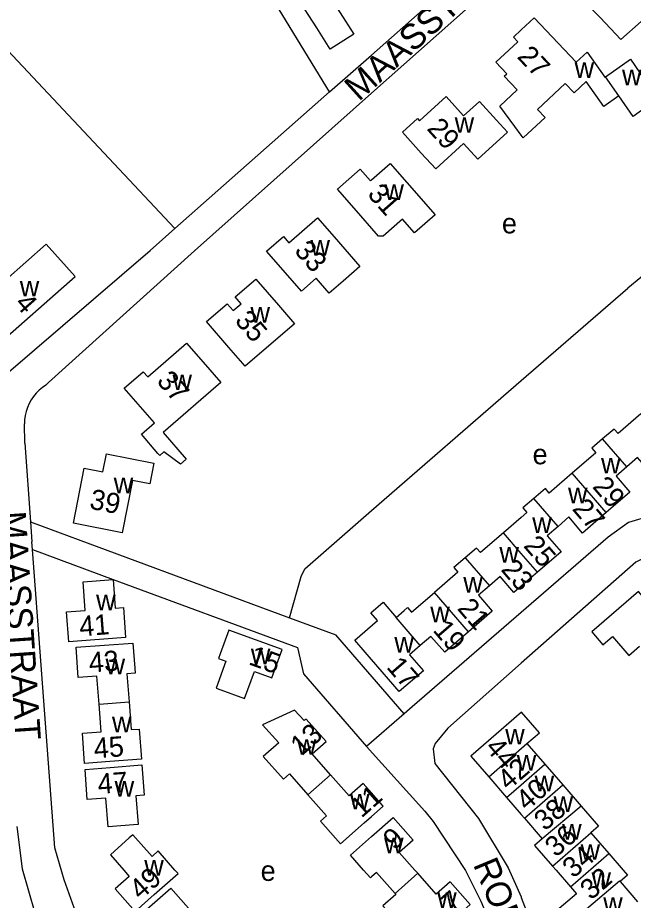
# Model space of a CAD drawing. Extents: x 156721 to 158827, y 386657 to 388950.
# Drawn here: x 157630 to 157751.8, y 387994 to 388168.6 of the extents above; entities that cross this region are included whole.
import ezdxf

# ---------------------------------------------------------------- set-up
doc = ezdxf.new("R2010")
doc.units = 0
for name, color, linetype in [('BLT_Basislijn', 7, 'Continuous'), ('BLT_Bebouwing', 7, 'Continuous'), ('BLT_Centroide', 7, 'Continuous'), ('BLT_Huisnummer', 7, 'Continuous'), ('BLT_Huisnummer_ tussenligend', 7, 'Continuous'), ('BLT_Onderverdeling_panden', 7, 'Continuous'), ('BLT_Straatnaam', 7, 'Continuous')]:
    doc.layers.add(name, color=color, linetype=linetype)

msp = doc.modelspace()

# ---------------------------------------------------------------- linework, layer by layer
at = {"layer": 'BLT_Basislijn'}
for p, q in [((157691.7, 388153.92), (157673, 388184.71)), ((157661.14, 388126.92), (157613.93, 388177.14)), ((157661.14, 388126.92), (157691.7, 388153.92)), ((157769.86, 388131.05), (157750.77, 388115.08)), ((157656.25, 388122.58), (157661.14, 388126.92)), ((157627.78, 388098.11), (157656.25, 388122.58)), ((157729.65, 388096.81), (157750.77, 388115.08)), ((157631.43, 388084.42), (157631.39, 388088.24)), ((157631.43, 388084.42), (157632.54, 388068.88)), ((157632.54, 388068.88), (157632.83, 388064.95)), ((157632.54, 388068.88), (157683.79, 388049.92)), ((157632.94, 388063.41), (157632.83, 388064.95)), ((157632.94, 388063.41), (157648.94, 388057.47)), ((157648.94, 388057.47), (157685.37, 388044.01)), ((157683.79, 388049.92), (157692.95, 388046.53)), ((157729.65, 388050.97), (157708.06, 388032.31)), ((157706.48, 388030.9), (157692.95, 388046.53)), ((157706.48, 388030.9), (157699.03, 388024.44)), ((157708.06, 388032.31), (157706.48, 388030.9)), ((157710.6, 388011.66), (157699.03, 388024.44)), ((157729.65, 387994.57), (157739.24, 387970.11))]:
    msp.add_line(p, q, dxfattribs=at)
for points in [[(157729.65, 388180.43), (157725.61, 388176.39), (157700, 388153.65), (157665, 388122.51), (157636.13, 388096.43), (157635.63, 388095.9)], [(157691.7, 388153.92), (157700, 388161.2), (157714.12, 388173.74)], [(157833.24, 388127.75), (157833.07, 388127.19), (157814.93, 388111.24), (157769.33, 388072.05), (157765.59, 388069.88), (157761.86, 388069.42), (157755.31, 388070.06), (157750.84, 388068.77), (157746.85, 388065.83), (157729.65, 388050.97)], [(157635.63, 388095.9), (157634.93, 388095.44), (157634.28, 388094.91), (157633.69, 388094.32), (157633.15, 388093.68), (157632.68, 388092.99), (157632.28, 388092.26), (157631.95, 388091.49), (157631.69, 388090.7), (157631.51, 388089.88), (157631.41, 388089.05), (157631.39, 388088.24)], [(157683.79, 388049.92), (157686.12, 388058.05), (157686.84, 388059.6), (157700, 388071.15), (157729.65, 388096.81)], [(157729.65, 387937.43), (157710.74, 387920.77), (157709.2, 387919.75), (157706.04, 387919.41), (157703.64, 387920.75), (157700, 387924.06), (157697.52, 387926.52), (157672, 387954.47), (157652.08, 387978.06), (157646.22, 387984.63), (157641.51, 387991.61), (157639.2, 387998.07), (157637.4, 388004.39), (157632.94, 388063.41)], [(157759.73, 388062.57), (157756.37, 388062.49), (157754.16, 388061.84), (157752.34, 388060.88), (157729.65, 388040.93)], [(157685.37, 388044.01), (157686.61, 388038.81), (157699.03, 388024.44)], [(157729.65, 388040.93), (157715.14, 388028.08), (157712.65, 388025.05), (157712.26, 388023.99), (157712.58, 388021.11), (157721.22, 388010.23), (157727.05, 388000.46), (157729.61, 387994.68), (157729.65, 387994.57)], [(157710.6, 388011.66), (157712.26, 388009.62), (157718.62, 387999.92), (157721.68, 387993.82), (157728.97, 387976.53), (157729.65, 387974.81)], [(157629.85, 388008.63), (157630.9, 388000.22), (157633.45, 387991.57), (157634.72, 387988.28)]]:
    msp.add_lwpolyline(points, dxfattribs=at)
at = {"layer": 'BLT_Bebouwing'}
for p, q in [((157754.65, 388151.07), (157751.8, 388149.07)), ((157729.65, 388069.77), (157726.12, 388066.72)), ((157732.86, 388058.92), (157729.65, 388056.14)), ((157730.79, 388025.01), (157734.33, 388020.92)), ((157734.33, 388020.92), (157737.87, 388016.84)), ((157723.21, 388018.46), (157726.75, 388014.37)), ((157737.87, 388016.84), (157741.5, 388012.65)), ((157726.75, 388014.37), (157729.65, 388011.01)), ((157729.65, 388011.01), (157730.29, 388010.28)), ((157730.29, 388010.28), (157733.82, 388006.19)), ((157743.42, 388007.37), (157746.96, 388003.29)), ((157749.19, 387997.71), (157752.62, 387993.75))]:
    msp.add_line(p, q, dxfattribs=at)
for points in [[(157757.45, 388171.78), (157749.17, 388180.36), (157747.48, 388178.73), (157745.28, 388181), (157739.51, 388175.42), (157742.17, 388172.67), (157741.76, 388172.28), (157745.25, 388168.66), (157749.35, 388164.3), (157753.37, 388167.84), (157757.45, 388171.78)], [(157693.83, 388169.55), (157696.52, 388165.33), (157691.88, 388162.37), (157689.19, 388166.58), (157685.17, 388172.87), (157689.82, 388175.84), (157693.83, 388169.55)], [(157729.65, 388166.18), (157732.22, 388168.6), (157740.53, 388159.77), (157742.69, 388161.8), (157746.22, 388156.84), (157746.32, 388156.91)], [(157729.65, 388145.34), (157728.38, 388147.06), (157725.39, 388151.07), (157728.85, 388154.32), (157726.29, 388157.04), (157726.8, 388157.51), (157724.65, 388159.79), (157728.96, 388163.85), (157728.12, 388164.74), (157729.65, 388166.18)], [(157746.32, 388156.91), (157751.25, 388160.36), (157754.12, 388156.26), (157756.73, 388152.53)], [(157748.97, 388153.12), (157745.97, 388151), (157742.48, 388155.96), (157740.1, 388153.72), (157738.36, 388155.57), (157732.89, 388150.42), (157734.36, 388148.86), (157730.05, 388144.8), (157729.65, 388145.34)], [(157724.75, 388148.35), (157726.91, 388145.98), (157721.04, 388140.63), (157718.24, 388143.7), (157712.73, 388138.68), (157709.86, 388141.83), (157706.13, 388145.93), (157709.1, 388148.64), (157709.51, 388148.19), (157714.77, 388152.99), (157718.24, 388149.19), (157721.38, 388152.05), (157724.75, 388148.35)], [(157751.8, 388149.07), (157748.97, 388153.12)], [(157700, 388136.5), (157703.73, 388139.78), (157707.03, 388136.02), (157712.64, 388129.62), (157708.54, 388126.02), (157706.16, 388128.72), (157702.35, 388125.38), (157701.4, 388125.41), (157696.58, 388130.89), (157693.29, 388134.65), (157697.79, 388138.61), (157699.8, 388136.33), (157700, 388136.5)], [(157692.63, 388125.23), (157697.74, 388119.37), (157694.42, 388116.47), (157691.68, 388114.09), (157689.09, 388117.06), (157686.18, 388114.52), (157682.56, 388118.67), (157679.27, 388122.44), (157682.59, 388125.33), (157683.69, 388124.07), (157689.34, 388129), (157692.63, 388125.23)], [(157619.5, 388109.58), (157625.19, 388103.16), (157641.41, 388117.38), (157635.7, 388123.8), (157619.5, 388109.58)], [(157677.16, 388116.91), (157681.6, 388111.76), (157684.78, 388108.06), (157675.02, 388099.64), (157671.83, 388103.35), (157667.39, 388108.51), (157671.47, 388112.02), (157672.65, 388110.65), (157674.23, 388112.01), (157673.05, 388113.38), (157677.16, 388116.91)], [(157666.71, 388100.43), (157670.2, 388096.42), (157658.82, 388086.52), (157663.39, 388081.26), (157662.24, 388080.26), (157658.97, 388082.75), (157658.13, 388082.02), (157657.78, 388082.42), (157654.5, 388086.2), (157657.07, 388088.43), (157651.11, 388095.29), (157654.88, 388098.57), (157655.78, 388097.54), (157663.43, 388104.2), (157666.71, 388100.43)], [(157753.34, 388090.25), (157748.81, 388086.33), (157748.02, 388087.24), (157745.76, 388085.28)], [(157745.76, 388085.28), (157743.6, 388083.42), (157744.39, 388082.51), (157739.73, 388078.49)], [(157643.22, 388079.49), (157646.89, 388078.77), (157647.6, 388082.36), (157657, 388080.5), (157656.19, 388076.4), (157652.74, 388077.08), (157650.69, 388066.7), (157641.07, 388068.59), (157643.22, 388079.49)], [(157760.09, 388082.49), (157755.42, 388078.43), (157752.67, 388081.6), (157750.54, 388079.75)], [(157750.54, 388079.75), (157748.41, 388077.91), (157751.14, 388074.75), (157746.47, 388070.71)], [(157739.73, 388078.49), (157735.2, 388074.57), (157734.42, 388075.48), (157732.14, 388073.51)], [(157732.14, 388073.51), (157729.98, 388071.64), (157730.76, 388070.73), (157729.65, 388069.77)], [(157746.47, 388070.71), (157741.8, 388066.66), (157739.07, 388069.84), (157736.93, 388067.99)], [(157736.93, 388067.99), (157734.8, 388066.13), (157737.53, 388062.96), (157732.86, 388058.92)], [(157726.12, 388066.72), (157721.58, 388062.79), (157720.79, 388063.7), (157718.57, 388061.78)], [(157718.57, 388061.78), (157716.35, 388059.86), (157717.13, 388058.95), (157712.48, 388054.93)], [(157648.94, 388057.47), (157649.35, 388051.81), (157650.94, 388051.92), (157651.36, 388045.98), (157640.16, 388045.12), (157639.72, 388051.08), (157643.4, 388051.36), (157642.99, 388057.03), (157648.94, 388057.47)], [(157729.65, 388056.14), (157728.19, 388054.88), (157725.46, 388058.06), (157723.36, 388056.24)], [(157723.36, 388056.24), (157721.19, 388054.36), (157723.9, 388051.19), (157719.23, 388047.14)], [(157754.73, 388052.89), (157752.84, 388055.08), (157743.6, 388047.11), (157745.82, 388044.54), (157747.72, 388046.17), (157750.92, 388042.46), (157753.04, 388044.29)], [(157704.89, 388049.96), (157706.5, 388051.35), (157707.16, 388051.92), (157707.95, 388051.01), (157712.48, 388054.93)], [(157698.78, 388043.09), (157696.73, 388045.47), (157701.24, 388049.38), (157699.93, 388050.89), (157702.35, 388052.99), (157704.89, 388049.96)], [(157670.2, 388035.65), (157674.9, 388033.94), (157676.86, 388039.27), (157680.32, 388038), (157682.39, 388043.6), (157671.79, 388047.48), (157670.08, 388042.78), (157669.74, 388041.86), (157671.24, 388041.31), (157669.3, 388035.98), (157670.2, 388035.65)], [(157719.23, 388047.14), (157714.56, 388043.09), (157711.79, 388046.23), (157709.69, 388044.41)], [(157646.13, 388032.85), (157645.72, 388038.37), (157642.02, 388038.1), (157641.58, 388044.06), (157652.82, 388044.9), (157653.19, 388039.91), (157653.26, 388038.94), (157651.66, 388038.82), (157652.07, 388033.28)], [(157705.5, 388035.29), (157700, 388041.67), (157698.78, 388043.09)], [(157709.69, 388044.41), (157707.58, 388042.59), (157710.3, 388039.44), (157705.5, 388035.29)], [(157652.07, 388033.28), (157652.48, 388027.78), (157654.09, 388027.9), (157654.53, 388021.93), (157648.27, 388021.46), (157643.28, 388021.09), (157642.83, 388027.05), (157646.53, 388027.32), (157646.13, 388032.85)], [(157691.94, 388018.84), (157688.28, 388022.98), (157691.04, 388025.42), (157687.08, 388029.88), (157686.74, 388029.58), (157684.83, 388031.65), (157678.5, 388028.73), (157681.69, 388025.14), (157678.63, 388022.44), (157682.59, 388017.95), (157683.79, 388019.01), (157687.45, 388014.87)], [(157730.79, 388025.01), (157733.27, 388027.15), (157729.73, 388031.24), (157719.68, 388022.55), (157723.21, 388018.46)], [(157652.92, 388008.92), (157647.93, 388008.55), (157647.5, 388014.2), (157643.81, 388013.94), (157643.37, 388019.9), (157648.36, 388020.29), (157654.62, 388020.79), (157655.06, 388014.81), (157653.44, 388014.69), (157653.86, 388008.99), (157652.92, 388008.92)], [(157687.45, 388014.87), (157691.11, 388010.72), (157689.91, 388009.67), (157693.87, 388005.19), (157698.58, 388009.35), (157700, 388010.6), (157702.33, 388012.66), (157700, 388015.3), (157698.37, 388017.15), (157695.6, 388014.7), (157691.94, 388018.84)], [(157741.5, 388012.65), (157744.93, 388008.7), (157743.42, 388007.37)], [(157704.68, 387995.39), (157701.02, 387999.54), (157700, 387998.64), (157699.81, 387998.49), (157698.48, 388000), (157695.86, 388002.96), (157700, 388006.62), (157704.31, 388010.43), (157708.27, 388005.94), (157705.51, 388003.5), (157708.61, 388000), (157709.17, 387999.36)], [(157657.06, 387995.14), (157661.77, 387999.31), (157661.15, 388000), (157657.81, 388003.78), (157656.62, 388002.72), (157652.84, 388006.99), (157652.12, 388006.35), (157648.38, 388003.03), (157651.01, 388000), (157652.11, 387998.74), (157649.35, 387996.31), (157653.31, 387991.83), (157657.06, 387995.14)], [(157733.82, 388006.19), (157732.3, 388004.88), (157735.83, 388000.8)], [(157746.96, 388003.29), (157749.82, 388000), (157750.68, 387999.01), (157749.19, 387997.71)], [(157704.68, 387995.39), (157704.85, 387995.2), (157702.27, 387992.93), (157705.84, 387988.9), (157706.93, 387988.83), (157707.73, 387989.54), (157711.12, 387985.7), (157715.82, 387989.86), (157719.57, 387993.17), (157715.6, 387997.66), (157712.84, 387995.22), (157709.17, 387999.36)], [(157735.83, 388000.8), (157736.53, 388000), (157739.37, 387996.72)], [(157662.25, 387982.77), (157658.59, 387986.91), (157655.82, 387984.47), (157651.86, 387988.95), (157655.61, 387992.26), (157660.31, 387996.42), (157664.27, 387991.94), (157663.08, 387990.88), (157666.74, 387986.74)], [(157739.37, 387996.72), (157740.59, 387995.31), (157737.18, 387992.37), (157739.5, 387989.69)]]:
    msp.add_lwpolyline(points, dxfattribs=at)
at = {"layer": 'BLT_Onderverdeling_panden'}
for p, q in [((157748.97, 388153.12), (157746.32, 388156.91)), ((157750.54, 388079.75), (157745.76, 388085.28)), ((157746.47, 388070.71), (157739.73, 388078.49)), ((157736.93, 388067.99), (157732.14, 388073.51)), ((157729.65, 388062.63), (157726.12, 388066.72)), ((157732.86, 388058.92), (157729.65, 388062.63)), ((157718.57, 388061.78), (157723.36, 388056.24)), ((157719.23, 388047.14), (157712.48, 388054.93)), ((157709.69, 388044.41), (157704.89, 388049.96)), ((157646.13, 388032.85), (157652.07, 388033.28)), ((157723.21, 388018.46), (157730.79, 388025.01)), ((157729.65, 388016.88), (157734.33, 388020.92)), ((157691.94, 388018.84), (157687.45, 388014.87)), ((157726.75, 388014.37), (157729.65, 388016.88)), ((157730.29, 388010.28), (157737.87, 388016.84)), ((157741.5, 388012.65), (157733.82, 388006.19)), ((157735.83, 388000.8), (157743.42, 388007.37)), ((157739.37, 387996.72), (157746.96, 388003.29)), ((157704.68, 387995.39), (157709.17, 387999.36))]:
    msp.add_line(p, q, dxfattribs=at)
msp.add_lwpolyline([(157749.19, 387997.71), (157749.09, 387997.81), (157739.5, 387989.69)], dxfattribs=at)

# ---------------------------------------------------------------- texts
at = {"layer": 'BLT_Centroide'}
for s, p in [('w', (157740.21, 388156.69)), ('w', (157749.59, 388155.24)), ('w', (157716.48, 388145.84)), ('w', (157702.58, 388132.56)), ('e', (157725.83, 388125.93)), ('w', (157687.95, 388121.53)), ('w', (157630.45, 388113.47)), ('w', (157676.09, 388108.28)), ('w', (157660.66, 388094.95)), ('e', (157731.9, 388080.26)), ('w', (157745.44, 388078.45)), ('w', (157649.03, 388074.55)), ('w', (157738.91, 388072.56)), ('w', (157731.83, 388066.67)), ('w', (157725.33, 388060.81)), ('w', (157718.19, 388054.89)), ('w', (157645.55, 388051.38)), ('w', (157711.66, 388049)), ('w', (157704.55, 388043.03)), ('w', (157676.17, 388040.72)), ('w', (157647.42, 388038.72)), ('w', (157648.69, 388027.27)), ('w', (157726.48, 388024.84)), ('w', (157685.28, 388022.81)), ('w', (157728.77, 388019.69)), ('w', (157732.3, 388015.59)), ('w', (157649.22, 388014.52)), ('w', (157695.78, 388012)), ('w', (157736.05, 388011.5)), ('w', (157737.74, 388006.03)), ('w', (157702.52, 388003.34)), ('w', (157741.39, 388002.03)), ('w', (157655.08, 387998.92)), ('e', (157678.1, 387997.86)), ('w', (157743.55, 387996.5)), ('w', (157713.03, 387992.53)), ('w', (157745.87, 387991.56))]:
    msp.add_text(s, height=4, dxfattribs=at).set_placement(p)
at = {"layer": 'BLT_Huisnummer'}
for s, rotation, p in [('27', 313.259, (157728.68, 388160.76)), ('29', 312.3487, (157710.83, 388146.55)), ('31', 311.2953, (157699.06, 388133.59)), ('33', 311.087, (157684.61, 388122.39)), ('4', 311.5742, (157629.28, 388111.95)), ('35', 310.6871, (157672.83, 388108.58)), ('37', 311.0221, (157657.37, 388096.62)), ('29', 310.7458, (157743.58, 388075.76)), ('39', 348.8551, (157644.07, 388071.52)), ('25', 310.7458, (157729.95, 388064.06)), ('21', 310.7458, (157716.84, 388051.67)), ('41', 4.3752, (157642.36, 388046.22)), ('43', 4.1857, (157644.24, 388039.06)), ('15', 339.9738, (157675.52, 388040.76)), ('17', 310.7458, (157702.84, 388040.08)), ('13', 41.3599, (157686.19, 388022.44)), ('45', 4.2644, (157645.24, 388022.1)), ('44', 310.837, (157722.34, 388024.13)), ('42', 40.8406, (157727.1, 388015.61)), ('47', 4.2432, (157645.99, 388015.05)), ('11', 41.4624, (157698.05, 388010.18)), ('38', 40.954, (157734.35, 388007.59)), ('9', 41.5135, (157704.54, 388003.8)), ('34', 40.954, (157739.96, 387998.24)), ('49', 41.4799, (157654.34, 387993.95)), ('7', 41.4727, (157716.07, 387991.29))]:
    msp.add_text(s, height=4, rotation=rotation, dxfattribs=at).set_placement(p)
at = {"layer": 'BLT_Huisnummer_ tussenligend'}
for s, rotation, p in [('27', 310.7458, (157739.58, 388071.37)), ('23', 310.7458, (157725.48, 388059.36)), ('19', 310.7458, (157712.02, 388047.38)), ('40', 40.954, (157730.75, 388011.57)), ('36', 40.954, (157736.51, 388002.39)), ('32', 40.954, (157743.46, 387993.92))]:
    msp.add_text(s, height=4, rotation=rotation, dxfattribs=at).set_placement(p)
at = {"layer": 'BLT_Straatnaam'}
for s, rotation, p in [('MAASSTRAAT', 42.1039, (157697.53, 388151.89)), ('MAASSTRAAT', 273.8355, (157626.62, 388070.83)), ('ROERSTRAAT', 292.5646, (157720.06, 388001.12))]:
    msp.add_text(s, height=5, rotation=rotation, dxfattribs=at).set_placement(p)

doc.saveas('drawing.dxf')
